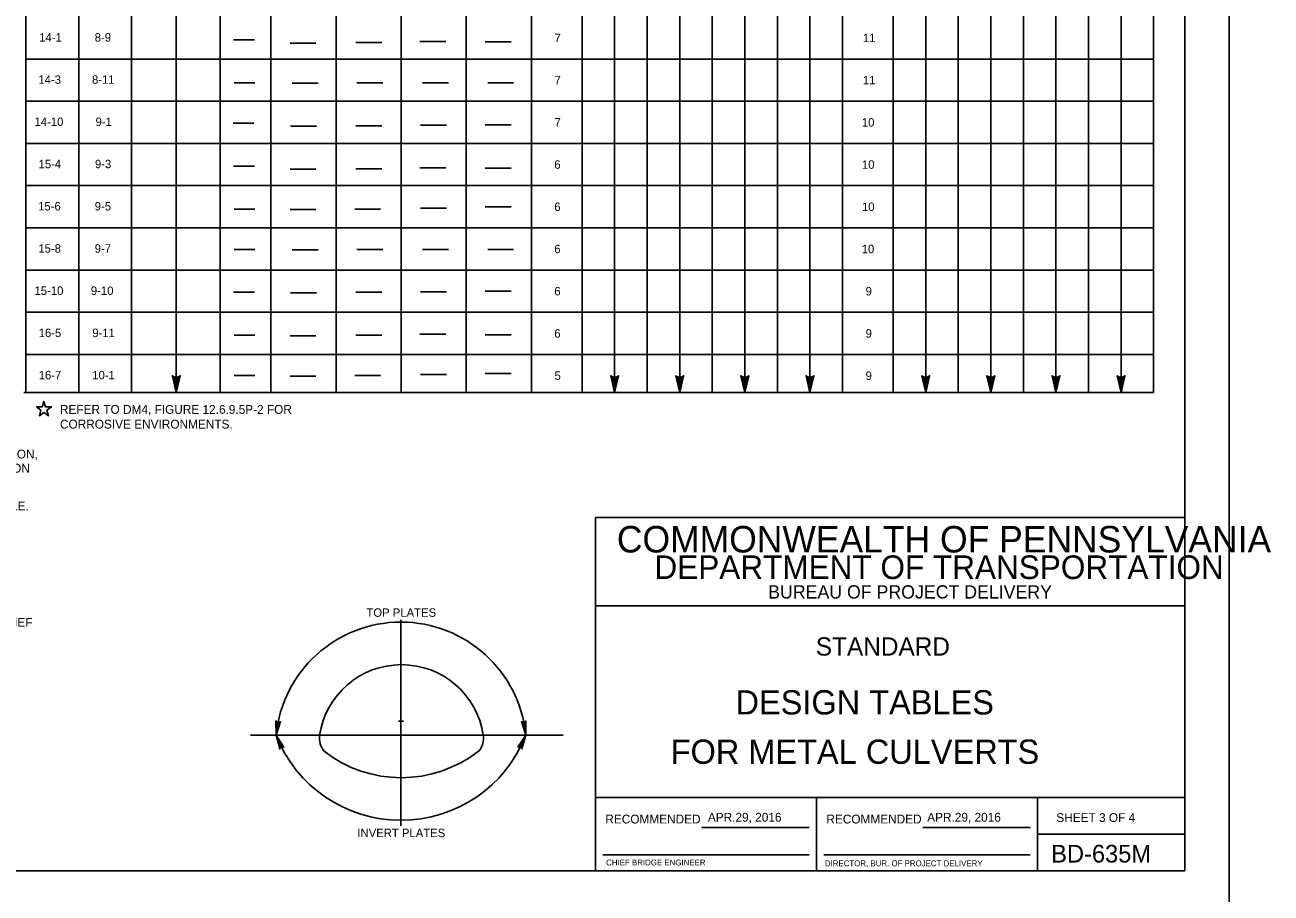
# Model space of a CAD drawing. Extents: x 591 to 2288, y -189 to 2187.
# Drawn here: x 1864.7 to 2287.6, y 1006.7 to 1301.4 of the extents above; entities that cross this region are included whole.
import ezdxf

# ---------------------------------------------------------------- set-up
doc = ezdxf.new("R2010")
doc.units = 0
for name, color, linetype in [('1', 7, 'Continuous'), ('2', 7, 'Continuous'), ('PLT-BNDY', 7, 'Continuous')]:
    doc.layers.add(name, color=color, linetype=linetype)

msp = doc.modelspace()

# ---------------------------------------------------------------- linework, layer by layer
at = {"layer": '1'}
for p, q in [((1865.08, 1485.59), (1865.08, 1176.64)), ((1900.91, 1485.59), (1900.91, 1176.64)), ((1931.01, 1485.59), (1931.01, 1176.64)), ((2247.72, 1485.59), (2247.72, 1176.64)), ((2036.58, 1473.72), (2036.58, 1176.64)), ((2142.15, 1473.72), (2142.15, 1176.64)), ((1948.19, 1461.85), (1948.19, 1176.64)), ((2053.76, 1461.85), (2053.76, 1176.64)), ((2159.33, 1461.85), (2159.33, 1176.64)), ((1992.38, 1451.82), (1992.38, 1176.64)), ((2097.95, 1451.82), (2097.95, 1176.64)), ((2203.52, 1451.82), (2203.52, 1176.64)), ((1883, 1434.62), (1883, 1176.64)), ((1970.29, 1437.48), (1970.29, 1176.64)), ((2014.48, 1437.48), (2014.48, 1176.64)), ((2075.86, 1437.48), (2075.86, 1176.64)), ((2120.05, 1437.48), (2120.05, 1176.64)), ((2181.43, 1437.48), (2181.43, 1176.64)), ((2225.62, 1437.48), (2225.62, 1176.64)), ((1916.1, 1407.43), (1916.1, 1176.64)), ((2064.81, 1407.43), (2064.81, 1176.64)), ((2086.91, 1407.43), (2086.91, 1176.64)), ((2109, 1407.43), (2109, 1176.64)), ((2131.1, 1407.43), (2131.1, 1176.64)), ((2170.38, 1407.43), (2170.38, 1176.64)), ((2192.48, 1407.43), (2192.48, 1176.64)), ((2214.57, 1407.43), (2214.57, 1176.64)), ((2236.67, 1407.43), (2236.67, 1176.64)), ((1935.55, 1296.36), (1942.58, 1296.36)), ((1954.69, 1295.3), (1963.48, 1295.3)), ((1977, 1295.48), (1985.78, 1295.48)), ((1998.77, 1295.83), (2007.55, 1295.83)), ((2020.9, 1295.65), (2029.68, 1295.65)), ((1865.08, 1289.86), (2247.72, 1289.86)), ((1935.73, 1281.78), (1942.75, 1281.78)), ((1955.4, 1281.61), (1964.18, 1281.61)), ((1977.35, 1281.78), (1986.13, 1281.78)), ((1999.65, 1281.78), (2008.43, 1281.78)), ((2021.78, 1281.78), (2030.55, 1281.78)), ((1865.08, 1275.53), (2247.72, 1275.53)), ((1935.38, 1268.08), (1942.4, 1268.08)), ((1954.87, 1267.03), (1963.65, 1267.03)), ((1977, 1267.2), (1985.78, 1267.2)), ((1998.95, 1267.38), (2007.73, 1267.38)), ((2020.9, 1267.56), (2029.68, 1267.56)), ((1865.08, 1261.2), (2247.72, 1261.2)), ((1935.55, 1253.51), (1942.58, 1253.51)), ((1954.69, 1252.45), (1963.48, 1252.45)), ((1977, 1252.63), (1985.78, 1252.63)), ((1998.77, 1252.98), (2007.55, 1252.98)), ((2020.9, 1252.8), (2029.68, 1252.8)), ((1865.08, 1246.87), (2247.72, 1246.87)), ((1998.95, 1239.28), (2007.73, 1239.28)), ((2020.9, 1239.64), (2029.68, 1239.64)), ((1935.73, 1238.93), (1942.75, 1238.93)), ((1954.69, 1238.76), (1963.48, 1238.76)), ((1976.64, 1238.93), (1985.42, 1238.93)), ((1865.08, 1232.54), (2247.72, 1232.54)), ((1935.73, 1225.24), (1942.75, 1225.24)), ((1955.4, 1225.06), (1964.18, 1225.06)), ((1977.35, 1225.24), (1986.13, 1225.24)), ((1999.65, 1225.24), (2008.43, 1225.24)), ((2021.78, 1225.24), (2030.55, 1225.24)), ((1865.08, 1218.2), (2247.72, 1218.2)), ((1935.55, 1210.66), (1942.58, 1210.66)), ((1954.87, 1210.49), (1963.65, 1210.49)), ((1977, 1210.66), (1985.78, 1210.66)), ((1998.95, 1210.84), (2007.73, 1210.84)), ((2020.9, 1211.01), (2029.68, 1211.01)), ((1865.08, 1203.87), (2247.72, 1203.87)), ((1935.73, 1196.09), (1942.75, 1196.09)), ((1954.69, 1195.91), (1963.48, 1195.91)), ((1977, 1196.09), (1985.78, 1196.09)), ((1998.77, 1196.44), (2007.55, 1196.44)), ((2020.9, 1196.26), (2029.68, 1196.26)), ((1865.08, 1189.54), (2247.72, 1189.54)), ((1935.73, 1182.39), (1942.75, 1182.39)), ((1954.69, 1182.21), (1963.48, 1182.21)), ((1976.64, 1182.39), (1985.42, 1182.39)), ((1998.95, 1182.74), (2007.73, 1182.74)), ((2020.9, 1183.09), (2029.68, 1183.09)), ((1864.37, 1176.64), (2247.72, 1176.64)), ((1992.31, 1029.59), (1992.31, 1099.53)), ((1991.5, 1065.06), (1993.14, 1065.06)), ((1941.26, 1060.31), (2047.31, 1060.31)), ((2018.74, 1054.88), (2018.65, 1054.88)), ((2133.34, 1014.21), (2133.34, 1039.21)), ((2208.34, 1039.21), (2208.34, 1014.21)), ((2094.43, 1028.93), (2130.84, 1028.93)), ((2169.43, 1028.93), (2205.84, 1028.93)), ((2060.84, 1019.71), (2130.84, 1019.71)), ((2135.84, 1019.71), (2205.84, 1019.71))]:
    msp.add_line(p, q, dxfattribs=at)
for points in [[(1917.08, 1182.06), (1916.51, 1181.86), (1916.1, 1176.64), (1917.08, 1182.06), (1917.42, 1182.34), (1916.1, 1176.64), (1915.73, 1181.86), (1915.16, 1182.05), (1916.1, 1176.64), (1914.79, 1182.34), (1915.16, 1182.05)], [(2065.79, 1182.06), (2065.23, 1181.86), (2064.81, 1176.64), (2065.79, 1182.06), (2066.13, 1182.34), (2064.81, 1176.64), (2064.44, 1181.86), (2063.88, 1182.05), (2064.81, 1176.64), (2063.51, 1182.34), (2063.88, 1182.05)], [(2087.89, 1182.06), (2087.32, 1181.86), (2086.91, 1176.64), (2087.89, 1182.06), (2088.23, 1182.34), (2086.91, 1176.64), (2086.54, 1181.86), (2085.98, 1182.05), (2086.91, 1176.64), (2085.6, 1182.34), (2085.98, 1182.05)], [(2109.98, 1182.06), (2109.42, 1181.86), (2109, 1176.64), (2109.98, 1182.06), (2110.33, 1182.34), (2109, 1176.64), (2108.63, 1181.86), (2108.07, 1182.05), (2109, 1176.64), (2107.7, 1182.34), (2108.07, 1182.05)], [(2132.08, 1182.06), (2131.52, 1181.86), (2131.1, 1176.64), (2132.08, 1182.06), (2132.43, 1182.34), (2131.1, 1176.64), (2130.73, 1181.86), (2130.17, 1182.05), (2131.1, 1176.64), (2129.8, 1182.34), (2130.17, 1182.05)], [(2171.36, 1182.06), (2170.8, 1181.86), (2170.38, 1176.64), (2171.36, 1182.06), (2171.7, 1182.34), (2170.38, 1176.64), (2170.01, 1181.86), (2169.45, 1182.05), (2170.38, 1176.64), (2169.08, 1182.34), (2169.45, 1182.05)], [(2193.46, 1182.06), (2192.89, 1181.86), (2192.48, 1176.64), (2193.46, 1182.06), (2193.8, 1182.34), (2192.48, 1176.64), (2192.11, 1181.86), (2191.55, 1182.05), (2192.48, 1176.64), (2191.17, 1182.34), (2191.55, 1182.05)], [(2215.55, 1182.06), (2214.99, 1181.86), (2214.57, 1176.64), (2215.55, 1182.06), (2215.9, 1182.34), (2214.57, 1176.64), (2214.2, 1181.86), (2213.64, 1182.05), (2214.57, 1176.64), (2213.27, 1182.34), (2213.64, 1182.05)], [(2237.65, 1182.06), (2237.09, 1181.86), (2236.67, 1176.64), (2237.65, 1182.06), (2238, 1182.34), (2236.67, 1176.64), (2236.3, 1181.86), (2235.74, 1182.05), (2236.67, 1176.64), (2235.37, 1182.34), (2235.74, 1182.05)], [(1951.18, 1064.71), (1950.83, 1064.6), (1949.94, 1060.31), (1951.18, 1064.71), (1951.42, 1064.91), (1949.94, 1060.31), (1950.38, 1064.66), (1950.08, 1064.87), (1949.94, 1060.31), (1949.9, 1065.14), (1950.08, 1064.87)], [(2034.56, 1064.88), (2034.25, 1064.67), (2034.67, 1060.31), (2034.56, 1064.88), (2034.72, 1065.15), (2034.67, 1060.31), (2033.8, 1064.6), (2033.46, 1064.71), (2034.67, 1060.31), (2033.21, 1064.92), (2033.46, 1064.71)], [(1951.3, 1055.93), (1951.53, 1056.23), (1949.94, 1060.31), (1951.3, 1055.93), (1951.22, 1055.64), (1949.94, 1060.31), (1951.94, 1056.42), (1952.3, 1056.4), (1949.94, 1060.31), (1952.61, 1056.27), (1952.3, 1056.4)], [(2032.27, 1056.4), (2032.64, 1056.42), (2034.67, 1060.31), (2032.27, 1056.4), (2031.99, 1056.28), (2034.67, 1060.31), (2033.06, 1056.24), (2033.29, 1055.96), (2034.67, 1060.31), (2033.39, 1055.65), (2033.29, 1055.96)]]:
    msp.add_lwpolyline(points, dxfattribs=at)
for centre, radius, start, end in [((1992.31, 1056.14), 42.57, 5.6241, 174.3759), ((1992.49, 1056.2), 28.06, 8.4323, 171.5893), ((1992.31, 1076.93), 45.51, 201.4219, 338.5781), ((1971.86, 1059.35), 7.2, 172.3667, 218.4979), ((2013.11, 1059.36), 7.2, 321.5021, 7.6333), ((1992.43, 1088.62), 42.73, 232.1732, 307.8489)]:
    msp.add_arc(centre, radius, start, end, dxfattribs=at)
at = {"layer": '2'}
for p, q in [((2258.34, 1578.21), (2258.34, 1014.21)), ((1871.12, 1170.86), (1871.12, 1170.86)), ((2258.34, 1134.21), (2058.34, 1134.21)), ((2058.34, 1134.21), (2058.34, 1014.21)), ((2258.34, 1014.21), (2258.34, 1134.21)), ((2258.34, 1104.21), (2058.34, 1104.21)), ((2258.34, 1039.21), (2058.34, 1039.21)), ((2208.34, 1026.71), (2258.34, 1026.71)), ((2258.34, 1014.21), (1472.34, 1014.21)), ((2058.34, 1014.21), (2258.34, 1014.21))]:
    msp.add_line(p, q, dxfattribs=at)
msp.add_lwpolyline([(1868.62, 1171.74), (1870.62, 1171.74), (1871.12, 1173.61), (1871.74, 1171.74), (1873.74, 1171.74), (1872.12, 1170.61), (1872.74, 1168.74), (1871.12, 1169.86), (1869.62, 1168.74), (1870.12, 1170.61), (1868.62, 1171.74)], dxfattribs=at)
at = {"layer": 'PLT-BNDY'}
msp.add_lwpolyline([(1432.34, 1593.21), (2273.34, 1593.21), (2273.34, 999.21), (1432.34, 999.21)], close=True, dxfattribs=at)

# ---------------------------------------------------------------- texts
at = {"layer": '1'}
for s, height, p in [('14-1', 2.866, (1869.56, 1295.78)), ('8-9', 2.866, (1888.4, 1295.78)), ('7', 2.87, (2044.42, 1295.6)), ('11', 2.866, (2149.05, 1295.6)), ('14-3', 2.866, (1869.28, 1281.45)), ('8-11', 2.866, (1887.47, 1281.45)), ('7', 2.87, (2044.42, 1281.27)), ('11', 2.866, (2149.05, 1281.27)), ('14-10', 2.866, (1867.96, 1267.12)), ('9-1', 2.866, (1888.69, 1267.12)), ('7', 2.87, (2044.42, 1266.93)), ('10', 2.866, (2148.73, 1266.93)), ('15-4', 2.866, (1869.35, 1252.79)), ('9-3', 2.866, (1888.48, 1252.79)), ('6', 2.87, (2044.35, 1252.6)), ('10', 2.866, (2148.75, 1252.6)), ('15-6', 2.866, (1869.21, 1238.45)), ('9-5', 2.866, (1888.41, 1238.45)), ('6', 2.87, (2044.35, 1238.27)), ('10', 2.866, (2148.77, 1238.27)), ('15-8', 2.866, (1869.28, 1224.12)), ('9-7', 2.866, (1888.41, 1224.12)), ('6', 2.87, (2044.35, 1223.94)), ('10', 2.866, (2148.67, 1223.94)), ('15-10', 2.866, (1867.97, 1209.79)), ('9-10', 2.866, (1887.1, 1209.79)), ('6', 2.87, (2044.35, 1209.61)), ('9', 2.87, (2149.98, 1209.61)), ('16-5', 2.866, (1869.39, 1195.46)), ('9-11', 2.866, (1887.58, 1195.46)), ('6', 2.87, (2044.35, 1195.27)), ('9', 2.87, (2149.98, 1195.27)), ('16-7', 2.866, (1869.39, 1181.13)), ('10-1', 2.866, (1887.58, 1181.13)), ('5', 2.87, (2044.42, 1180.94)), ('9', 2.87, (2149.98, 1180.94)), ('7. THESE DESIGN VALUES ARE BASED UPON ASSUMPTION THAT THE EXCAVATION,', 3, (1704.58, 1154.26)), ('   BACKFILL AND CONSTRUCTION METHODS IN RC STANDARDS AND PUBLICATION', 3, (1704.58, 1149.44)), ('8. PIPE-ARCHES ARE DESIGNED FOR THE FILL HEIGHT INDICATED IN THIS TABLE.', 3, (1705.76, 1136.64)), ('TOP PLATES', 2.866, (1980.61, 1100.51)), ('RECOMMENDED', 3, (2061.67, 1030.34)), ('RECOMMENDED', 3, (2136.67, 1030.34)), ('INVERT PLATES', 2.8664, (1977.53, 1025.7)), ('CHIEF BRIDGE ENGINEER', 2.0003, (2061.93, 1016.09)), ('DIRECTOR, BUR. OF PROJECT DELIVERY', 2.0003, (2136.17, 1015.81))]:
    msp.add_text(s, height=height, dxfattribs=at).set_placement(p)
at = {"layer": '2'}
for s, height, p in [('REFER TO DM4, FIGURE 12.6.9.5P-2 FOR', 3, (1876.62, 1169.41)), ('CORROSIVE ENVIRONMENTS.', 3, (1876.62, 1164.41)), ('COMMONWEALTH OF PENNSYLVANIA', 9, (2065.59, 1122.34)), ('DEPARTMENT OF TRANSPORTATION', 8.0002, (2078.34, 1113.34)), ('BUREAU OF PROJECT DELIVERY', 4.5, (2116.93, 1106.71)), ('10. PIPE MAY NOT BE PLACED WITHIN THE PAVEMENT STRUCTURE WITHOUT CHIEF', 3, (1701.9, 1097.11)), ('STANDARD', 6.188, (2133.09, 1087.34)), ('DESIGN TABLES', 8.2515, (2105.84, 1067.34)), ('FOR METAL CULVERTS', 8.2515, (2083.84, 1050.59)), ('APR.29, 2016', 3, (2096.47, 1030.95)), ('APR.29, 2016', 3, (2170.89, 1030.95)), ('SHEET 3 OF 4', 3, (2214.71, 1030.84)), ('BD-635M', 6, (2212.96, 1017.09))]:
    msp.add_text(s, height=height, dxfattribs=at).set_placement(p)

doc.saveas('drawing.dxf')
